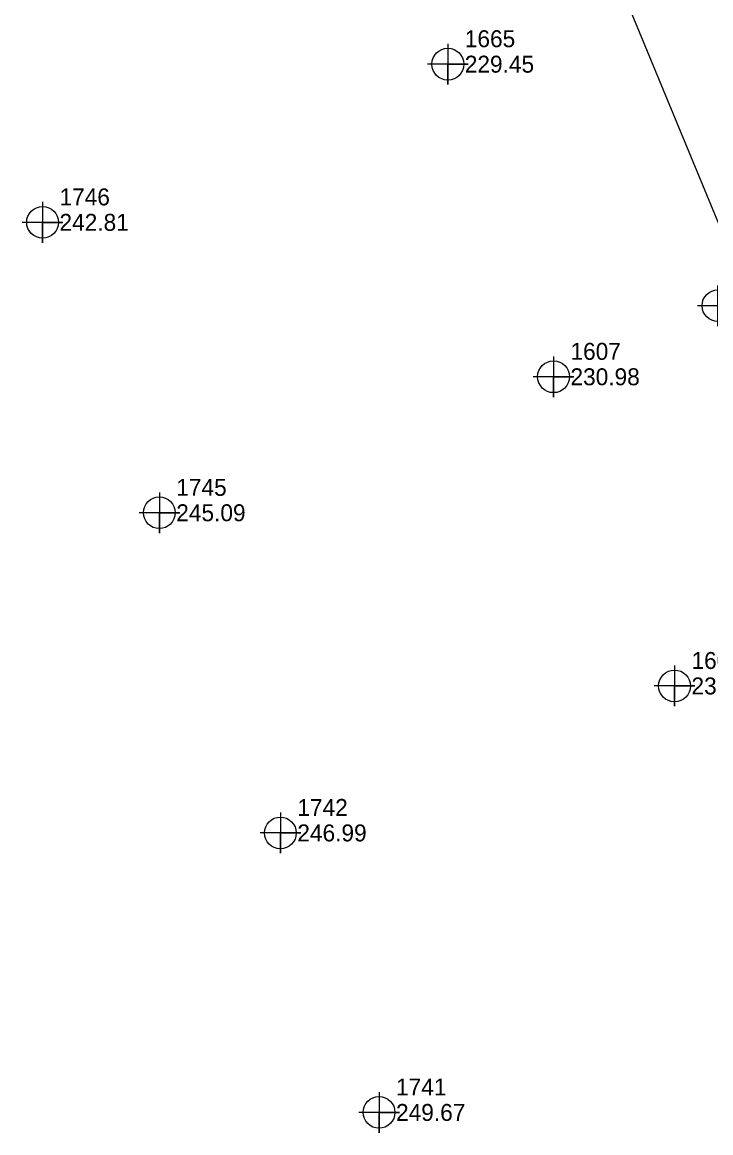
# Model space of a CAD drawing. Extents: x 2130621 to 2131998, y 642516 to 644503.
# Drawn here: x 2130981 to 2131082.6, y 643873.1 to 644036.8 of the extents above; entities that cross this region are included whole.
import ezdxf

# ---------------------------------------------------------------- set-up
doc = ezdxf.new("R2010")
doc.units = 0
for name, color, linetype in [('Exist Other Culture Fence Line Cogo Elevation', 7, 'Continuous'), ('Exist Other Culture Fence Line Cogo Number', 7, 'Continuous'), ('Exist Other Culture Fence Line Cogo Point CELL', 7, 'Continuous'), ('Exist Roads EOP', 7, 'Continuous'), ('Exist Roads Soil Cogo Point CELL', 7, 'Continuous'), ('Exist Vegetation Woods Line Cogo Elevation', 7, 'Continuous'), ('Exist Vegetation Woods Line Cogo Number', 7, 'Continuous'), ('Exist Vegetation Woods Line Cogo Point CELL', 7, 'Continuous')]:
    doc.layers.add(name, color=color, linetype=linetype)

msp = doc.modelspace()

# ---------------------------------------------------------------- linework, layer by layer
at = {"layer": 'Exist Other Culture Fence Line Cogo Point CELL'}
for points in [[(2130984.04, 644010.29), (2130984.04, 644004.29), (2130984.04, 644007.29), (2130987.04, 644007.29), (2130981.04, 644007.29)], [(2131001.27, 643967.47), (2131001.27, 643961.47), (2131001.27, 643964.47), (2131004.27, 643964.47), (2130998.27, 643964.47)], [(2131019.13, 643920.27), (2131019.13, 643914.27), (2131019.13, 643917.27), (2131022.13, 643917.27), (2131016.13, 643917.27)], [(2131033.69, 643879.06), (2131033.69, 643873.06), (2131033.69, 643876.06), (2131036.69, 643876.06), (2131030.69, 643876.06)]]:
    msp.add_lwpolyline(points, dxfattribs=at)
for centre in [(2130984.04, 644007.29), (2131001.27, 643964.47), (2131019.13, 643917.27), (2131033.69, 643876.06)]:
    msp.add_circle(centre, 2.34, dxfattribs=at)
at = {"layer": 'Exist Roads EOP'}
msp.add_lwpolyline([(2131091.53, 643988.04), (2131088.18, 643996.52), (2131069.48, 644041.65), (2131049.16, 644087.39), (2131027.85, 644132.11), (2131005.29, 644177.62)], dxfattribs=at)
at = {"layer": 'Exist Roads Soil Cogo Point CELL'}
msp.add_lwpolyline([(2131083.67, 643992), (2131083.67, 643998), (2131083.67, 643995), (2131086.67, 643995), (2131080.67, 643995)], dxfattribs=at)
msp.add_circle((2131083.67, 643995), 2.34, dxfattribs=at)
at = {"layer": 'Exist Vegetation Woods Line Cogo Point CELL'}
for points in [[(2131043.83, 644033.61), (2131043.83, 644027.61), (2131043.83, 644030.61), (2131046.83, 644030.61), (2131040.83, 644030.61)], [(2131059.42, 643987.52), (2131059.42, 643981.52), (2131059.42, 643984.52), (2131062.42, 643984.52), (2131056.42, 643984.52)], [(2131077.27, 643941.94), (2131077.27, 643935.94), (2131077.27, 643938.94), (2131080.27, 643938.94), (2131074.27, 643938.94)]]:
    msp.add_lwpolyline(points, dxfattribs=at)
for centre in [(2131043.83, 644030.61), (2131059.42, 643984.52), (2131077.27, 643938.94)]:
    msp.add_circle(centre, 2.34, dxfattribs=at)

# ---------------------------------------------------------------- texts
at = {"layer": 'Exist Other Culture Fence Line Cogo Elevation'}
for s, p in [('242.81', (2130986.54, 644006.04)), ('245.09', (2131003.77, 643963.22)), ('246.99', (2131021.63, 643916.02)), ('249.67', (2131036.19, 643874.81))]:
    msp.add_text(s, height=2.5, dxfattribs=at).set_placement(p)
at = {"layer": 'Exist Other Culture Fence Line Cogo Number'}
for s, p in [('1746', (2130986.54, 644009.79)), ('1745', (2131003.77, 643966.97)), ('1742', (2131021.63, 643919.77)), ('1741', (2131036.19, 643878.56))]:
    msp.add_text(s, height=2.5, dxfattribs=at).set_placement(p)
at = {"layer": 'Exist Vegetation Woods Line Cogo Elevation'}
for s, p in [('229.45', (2131046.33, 644029.36)), ('230.98', (2131061.92, 643983.27)), ('231.85', (2131079.77, 643937.69))]:
    msp.add_text(s, height=2.5, dxfattribs=at).set_placement(p)
at = {"layer": 'Exist Vegetation Woods Line Cogo Number'}
for s, p in [('1665', (2131046.33, 644033.11)), ('1607', (2131061.92, 643987.02)), ('1604', (2131079.77, 643941.44))]:
    msp.add_text(s, height=2.5, dxfattribs=at).set_placement(p)

doc.saveas('drawing.dxf')
